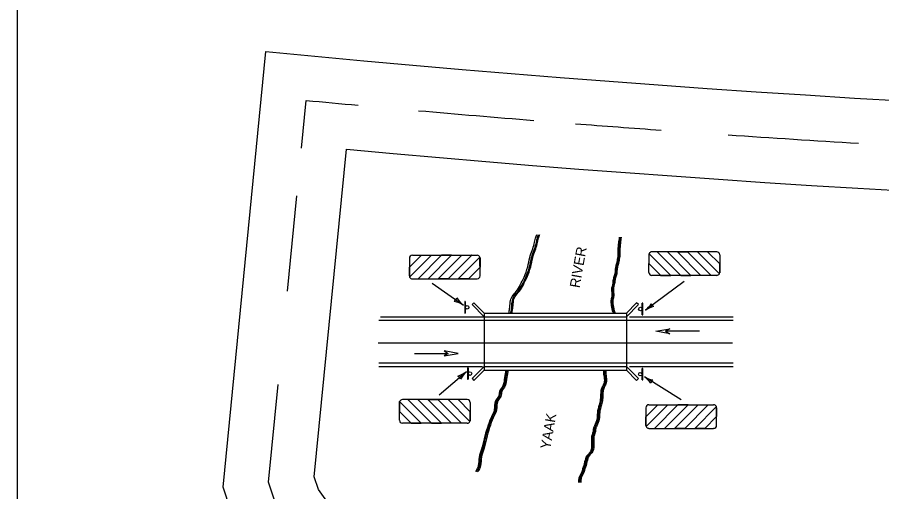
# Model space of a CAD drawing. Extents: x 49991.4 to 50021, y 49987.6 to 50011.4.
# Drawn here: x 50000.336 to 50002.261, y 50007.015 to 50008.071 of the extents above; entities that cross this region are included whole.
import ezdxf

# ---------------------------------------------------------------- set-up
doc = ezdxf.new("R2010")
doc.units = 0
for name, color, linetype in [('Level 1', 7, 'Continuous'), ('Level 2', 7, 'Continuous'), ('Level 3', 7, 'Continuous'), ('Level 4', 7, 'Continuous'), ('Level 5', 7, 'Continuous'), ('Level 7', 7, 'Continuous'), ('Level 8', 7, 'Continuous')]:
    doc.layers.add(name, color=color, linetype=linetype)

msp = doc.modelspace()

# ---------------------------------------------------------------- linework, layer by layer
at = {"layer": 'Level 1'}
for p, q in [((50001.3323, 50007.4382), (50001.3323, 50007.4126)), ((50001.3336, 50007.4382), (50001.3323, 50007.4382)), ((50001.3324, 50007.4382), (50001.3324, 50007.4126)), ((50001.3326, 50007.4382), (50001.3326, 50007.4126)), ((50001.3327, 50007.4382), (50001.3327, 50007.4126)), ((50001.3329, 50007.4382), (50001.3329, 50007.4126)), ((50001.333, 50007.4382), (50001.333, 50007.4126)), ((50001.3332, 50007.4382), (50001.3332, 50007.4126)), ((50001.3333, 50007.4382), (50001.3333, 50007.4126)), ((50001.3336, 50007.4382), (50001.3336, 50007.4126)), ((50001.3485, 50007.4314), (50001.3525, 50007.4353)), ((50001.3753, 50007.4045), (50001.3485, 50007.4314)), ((50001.3525, 50007.4353), (50001.3753, 50007.4125)), ((50001.7151, 50007.4353), (50001.6923, 50007.4125)), ((50001.6923, 50007.4045), (50001.719, 50007.4314)), ((50001.719, 50007.4314), (50001.7151, 50007.4353)), ((50001.729, 50007.4344), (50001.7277, 50007.4344)), ((50001.7277, 50007.4089), (50001.7277, 50007.4344)), ((50001.7279, 50007.4089), (50001.7279, 50007.4344)), ((50001.728, 50007.4089), (50001.728, 50007.4344)), ((50001.7281, 50007.4089), (50001.7281, 50007.4344)), ((50001.7284, 50007.4089), (50001.7284, 50007.4344)), ((50001.7284, 50007.4089), (50001.7284, 50007.4344)), ((50001.7287, 50007.4089), (50001.7287, 50007.4344)), ((50001.7288, 50007.4089), (50001.7288, 50007.4344)), ((50001.729, 50007.4089), (50001.729, 50007.4344)), ((50001.3323, 50007.4126), (50001.3336, 50007.4126)), ((50001.3753, 50007.4125), (50001.6923, 50007.4125)), ((50001.3753, 50007.4125), (50001.3753, 50007.2857)), ((50001.3753, 50007.4045), (50001.6923, 50007.4045)), ((50001.6923, 50007.4125), (50001.6923, 50007.2857)), ((50001.7277, 50007.4089), (50001.729, 50007.4089)), ((50001.1409, 50007.3966), (50001.9305, 50007.3966)), ((50001.1409, 50007.3017), (50001.9305, 50007.3017)), ((50001.3387, 50007.2908), (50001.3387, 50007.2652)), ((50001.3399, 50007.2908), (50001.3387, 50007.2908)), ((50001.3388, 50007.2908), (50001.3388, 50007.2652)), ((50001.339, 50007.2908), (50001.339, 50007.2652)), ((50001.3391, 50007.2908), (50001.3391, 50007.2652)), ((50001.3393, 50007.2908), (50001.3393, 50007.2652)), ((50001.3395, 50007.2908), (50001.3395, 50007.2652)), ((50001.3396, 50007.2908), (50001.3396, 50007.2652)), ((50001.3398, 50007.2908), (50001.3398, 50007.2652)), ((50001.3399, 50007.2908), (50001.3399, 50007.2652)), ((50001.3753, 50007.2937), (50001.3485, 50007.2668)), ((50001.3525, 50007.2629), (50001.3753, 50007.2857)), ((50001.3753, 50007.2937), (50001.6923, 50007.2937)), ((50001.3753, 50007.2857), (50001.6923, 50007.2857)), ((50001.6923, 50007.2937), (50001.719, 50007.2668)), ((50001.7151, 50007.2629), (50001.6923, 50007.2857)), ((50001.7288, 50007.2894), (50001.7275, 50007.2894)), ((50001.7275, 50007.2639), (50001.7275, 50007.2894)), ((50001.7277, 50007.2639), (50001.7277, 50007.2894)), ((50001.7278, 50007.2639), (50001.7278, 50007.2894)), ((50001.728, 50007.2639), (50001.728, 50007.2894)), ((50001.7281, 50007.2639), (50001.7281, 50007.2894)), ((50001.7284, 50007.2639), (50001.7284, 50007.2894)), ((50001.7284, 50007.2639), (50001.7284, 50007.2894)), ((50001.7287, 50007.2639), (50001.7287, 50007.2894)), ((50001.7288, 50007.2639), (50001.7288, 50007.2894)), ((50001.3485, 50007.2668), (50001.3525, 50007.2629)), ((50001.719, 50007.2668), (50001.7151, 50007.2629)), ((50001.3387, 50007.2652), (50001.3399, 50007.2652)), ((50001.7275, 50007.2639), (50001.7288, 50007.2639))]:
    msp.add_line(p, q, dxfattribs=at)
msp.add_lwpolyline([(50008.6146, 50011.2628), (50000.3356, 50011.2628), (50000.3356, 50000.0624), (50008.6146, 50000.0624)], close=True, dxfattribs=at)
for points in [[(50001.3799, 50005.8788), (50001.3215, 50006.0357), (50001.2141, 50006.2028), (50001.0765, 50006.3734), (50000.9542, 50006.4839), (50000.9664, 50006.5396), (50000.9328, 50006.5667), (50000.9328, 50006.7245), (50000.9084, 50006.799), (50000.9055, 50006.8175), (50000.8262, 50006.9283), (50000.7939, 50007.0252), (50000.8896, 50007.995)], [(50000.9689, 50007.7798), (50000.9793, 50007.8859)], [(50001.5508, 50005.9931), (50001.5014, 50006.1257), (50001.3765, 50006.32), (50001.2223, 50006.5113), (50001.1745, 50006.5544), (50001.1883, 50006.6177), (50001.1328, 50006.6624), (50001.1328, 50006.7565), (50001.1035, 50006.8459), (50001.0958, 50006.8953), (50001.0064, 50007.0202), (50000.9971, 50007.048), (50001.0691, 50007.7771)], [(50000.9374, 50007.4612), (50000.9584, 50007.6736)], [(50001.3341, 50007.4235), (50001.3357, 50007.4219)], [(50001.7271, 50007.4236), (50001.7256, 50007.4252)], [(50001.3405, 50007.276), (50001.3422, 50007.2744)], [(50001.7269, 50007.2785), (50001.7253, 50007.2801)], [(50000.9585, 50006.9153), (50000.9163, 50006.9742), (50000.8955, 50007.0366), (50000.9169, 50007.2536)]]:
    msp.add_lwpolyline(points, dxfattribs=at)
for centre in [(50001.3376, 50007.4254), (50001.7236, 50007.4217), (50001.344, 50007.278), (50001.7234, 50007.2766)]:
    msp.add_circle(centre, 0.004, dxfattribs=at)
for radius, start, end in [(36.1468, 264.4363, 275.54852), (36.2468, 264.59416, 264.77729), (36.2468, 264.99114, 265.3982), (36.2468, 265.54598, 265.84775), (36.2468, 266.08454, 266.54488), (36.3468, 264.75129, 275.22467)]:
    msp.add_arc((50004.3941, 50043.9715), radius, start, end, dxfattribs=at)
for points in [[(50001.4305, 50007.4124), (50001.4323, 50007.4224), (50001.4379, 50007.4499), (50001.447, 50007.4607), (50001.4561, 50007.4754), (50001.4643, 50007.4927), (50001.4725, 50007.5156), (50001.4772, 50007.5366), (50001.4872, 50007.5667), (50001.4899, 50007.5795), (50001.4926, 50007.5876)], [(50001.4346, 50007.4123), (50001.4365, 50007.4223), (50001.4419, 50007.4497), (50001.4511, 50007.4607), (50001.4602, 50007.4753), (50001.4685, 50007.4926), (50001.4767, 50007.5154), (50001.4812, 50007.5365), (50001.4912, 50007.5665), (50001.494, 50007.5793), (50001.4967, 50007.5876)], [(50001.4373, 50007.4125), (50001.4391, 50007.4225), (50001.4446, 50007.4499), (50001.4538, 50007.4609), (50001.4629, 50007.4755), (50001.471, 50007.4928), (50001.4793, 50007.5156), (50001.4839, 50007.5366), (50001.4939, 50007.5667), (50001.4966, 50007.5795), (50001.4993, 50007.5878)], [(50001.6635, 50007.4125), (50001.6617, 50007.418), (50001.6589, 50007.4335), (50001.6589, 50007.4427), (50001.6608, 50007.4517), (50001.6599, 50007.4655), (50001.6626, 50007.4791), (50001.6635, 50007.4874), (50001.6662, 50007.4965), (50001.669, 50007.5147), (50001.6708, 50007.5239), (50001.6735, 50007.5357), (50001.6744, 50007.5467), (50001.6744, 50007.5576), (50001.6753, 50007.5686), (50001.6762, 50007.575), (50001.6771, 50007.5813)], [(50001.6658, 50007.4127), (50001.6639, 50007.4181), (50001.6612, 50007.4337), (50001.6612, 50007.4427), (50001.663, 50007.452), (50001.6621, 50007.4656), (50001.6649, 50007.4793), (50001.6658, 50007.4875), (50001.6685, 50007.4967), (50001.6712, 50007.5149), (50001.6731, 50007.524), (50001.6758, 50007.5359), (50001.6767, 50007.5468), (50001.6767, 50007.5578), (50001.6776, 50007.5687), (50001.6785, 50007.5752), (50001.6795, 50007.5816)], [(50001.6678, 50007.4125), (50001.666, 50007.418), (50001.6632, 50007.4335), (50001.6632, 50007.4427), (50001.6651, 50007.4517), (50001.6641, 50007.4655), (50001.6669, 50007.4791), (50001.6678, 50007.4874), (50001.6705, 50007.4965), (50001.6732, 50007.5147), (50001.6752, 50007.5239), (50001.6779, 50007.5357), (50001.6788, 50007.5467), (50001.6788, 50007.5576), (50001.6797, 50007.5686), (50001.6806, 50007.575), (50001.6815, 50007.5813)], [(50001.4237, 50007.2856), (50001.4209, 50007.2692), (50001.4173, 50007.251), (50001.41, 50007.2381), (50001.4072, 50007.2272), (50001.4008, 50007.2171), (50001.3981, 50007.197), (50001.3909, 50007.1797), (50001.3827, 50007.1578), (50001.3753, 50007.1331), (50001.3698, 50007.1094), (50001.3643, 50007.0921), (50001.3625, 50007.0729), (50001.3561, 50007.0593)], [(50001.4262, 50007.2858), (50001.4233, 50007.2693), (50001.4197, 50007.251), (50001.4125, 50007.2384), (50001.4097, 50007.2273), (50001.4034, 50007.2173), (50001.4005, 50007.1973), (50001.3932, 50007.1799), (50001.3851, 50007.158), (50001.3777, 50007.1334), (50001.3723, 50007.1096), (50001.3668, 50007.0923), (50001.365, 50007.0731), (50001.3585, 50007.0594)], [(50001.4287, 50007.2856), (50001.426, 50007.2692), (50001.4224, 50007.251), (50001.4151, 50007.2381), (50001.4124, 50007.2272), (50001.4059, 50007.2171), (50001.4032, 50007.197), (50001.3959, 50007.1797), (50001.3877, 50007.1578), (50001.3804, 50007.1331), (50001.3749, 50007.1094), (50001.3694, 50007.0921), (50001.3675, 50007.0729), (50001.3612, 50007.0593)], [(50001.6414, 50007.2857), (50001.6414, 50007.2766), (50001.6433, 50007.263), (50001.6405, 50007.2519), (50001.6369, 50007.2447), (50001.6351, 50007.2355), (50001.6342, 50007.22), (50001.6315, 50007.2081), (50001.6278, 50007.1908), (50001.6269, 50007.1762), (50001.6213, 50007.1616), (50001.6186, 50007.1533), (50001.6186, 50007.1524), (50001.615, 50007.1379), (50001.615, 50007.1178), (50001.6105, 50007.1013), (50001.6041, 50007.0949), (50001.5994, 50007.0813), (50001.5949, 50007.0658), (50001.5922, 50007.0575), (50001.5867, 50007.0456), (50001.5858, 50007.0356)], [(50001.6438, 50007.2859), (50001.6438, 50007.2768), (50001.6456, 50007.2631), (50001.6429, 50007.2522), (50001.6393, 50007.2448), (50001.6375, 50007.2357), (50001.6366, 50007.2202), (50001.6338, 50007.2083), (50001.6302, 50007.191), (50001.6293, 50007.1763), (50001.6237, 50007.1617), (50001.621, 50007.1535), (50001.621, 50007.1526), (50001.6174, 50007.138), (50001.6174, 50007.118), (50001.6128, 50007.1016), (50001.6064, 50007.0951), (50001.6018, 50007.0814), (50001.5973, 50007.0659), (50001.5946, 50007.0577), (50001.5891, 50007.0458), (50001.5882, 50007.0358)], [(50001.6438, 50007.2859), (50001.6438, 50007.2768), (50001.6456, 50007.2631), (50001.6429, 50007.2522), (50001.6393, 50007.2448), (50001.6375, 50007.2357), (50001.6366, 50007.2202), (50001.6338, 50007.2083), (50001.6302, 50007.191), (50001.6293, 50007.1763), (50001.6237, 50007.1617), (50001.621, 50007.1535), (50001.621, 50007.1526), (50001.6174, 50007.138), (50001.6174, 50007.118), (50001.6128, 50007.1016), (50001.6064, 50007.0951), (50001.6018, 50007.0814), (50001.5973, 50007.0659), (50001.5946, 50007.0577), (50001.5891, 50007.0458), (50001.5882, 50007.0358)], [(50001.6465, 50007.2859), (50001.6465, 50007.2768), (50001.6483, 50007.2631), (50001.6456, 50007.2522), (50001.642, 50007.2448), (50001.6402, 50007.2357), (50001.6393, 50007.2202), (50001.6366, 50007.2083), (50001.6329, 50007.191), (50001.632, 50007.1763), (50001.6265, 50007.1617), (50001.6237, 50007.1535), (50001.6237, 50007.1526), (50001.6201, 50007.138), (50001.6201, 50007.118), (50001.6155, 50007.1016), (50001.6092, 50007.0951), (50001.6046, 50007.0814), (50001.6, 50007.0659), (50001.5973, 50007.0577), (50001.5918, 50007.0458), (50001.5909, 50007.0358)]]:
    msp.add_spline(points, degree=3, dxfattribs=at)
at = {"layer": 'Level 3'}
for p, q in [((50001.2598, 50007.4793), (50001.3293, 50007.4301)), ((50001.821, 50007.4826), (50001.7347, 50007.419)), ((50001.2756, 50007.2305), (50001.336, 50007.2829)), ((50001.8142, 50007.2193), (50001.7325, 50007.2706))]:
    msp.add_line(p, q, dxfattribs=at)
for centre, radius, start, end in [((50001.2999, 50007.451), 0.0154, 306.8721, 342.5944), ((50001.3675, 50007.4797), 0.0625, 212.1892, 232.3728), ((50001.2942, 50007.3749), 0.0655, 57.5606, 76.8104), ((50001.6975, 50007.4647), 0.059, 309.2289, 328.4787), ((50001.7663, 50007.3724), 0.0563, 103.8576, 124.0411), ((50001.7609, 50007.4383), 0.0139, 198.5404, 234.2627), ((50001.297, 50007.3318), 0.0625, 288.3958, 308.5793), ((50001.3088, 50007.2593), 0.0154, 23.0786, 58.8009), ((50001.3814, 50007.2356), 0.0655, 133.7671, 153.0169), ((50001.7007, 50007.2242), 0.0563, 35.3328, 55.5163), ((50001.7614, 50007.322), 0.059, 240.7041, 259.9539), ((50001.76, 50007.2534), 0.0139, 130.0156, 165.738)]:
    msp.add_arc(centre, radius, start, end, dxfattribs=at)
at = {"layer": 'Level 4'}
for p, q in [((50001.1444, 50007.4045), (50001.3753, 50007.4045)), ((50001.6996, 50007.4045), (50001.9305, 50007.4045)), ((50001.1409, 50007.2937), (50001.3718, 50007.2937)), ((50001.6996, 50007.2937), (50001.9305, 50007.2937))]:
    msp.add_line(p, q, dxfattribs=at)
at = {"layer": 'Level 5'}
msp.add_line((50001.1391, 50007.3467), (50001.9287, 50007.3467), dxfattribs=at)
at = {"layer": 'Level 7'}
for p, q in [((50001.855, 50007.3722), (50001.7796, 50007.3722)), ((50001.2202, 50007.323), (50001.2957, 50007.323))]:
    msp.add_line(p, q, dxfattribs=at)
for points in [[(50001.7891, 50007.3666), (50001.7577, 50007.3722), (50001.7891, 50007.3777), (50001.7796, 50007.3722)], [(50001.2861, 50007.3176), (50001.3175, 50007.323), (50001.2861, 50007.3287), (50001.2957, 50007.323)]]:
    msp.add_lwpolyline(points, close=True, dxfattribs=at)
at = {"layer": 'Level 8'}
for p, q in [((50001.209, 50007.5145), (50001.2358, 50007.5414)), ((50001.2583, 50007.5414), (50001.2096, 50007.4927)), ((50001.2156, 50007.5413), (50001.36, 50007.5413)), ((50001.2807, 50007.5414), (50001.2282, 50007.4888)), ((50001.2355, 50007.5414), (50001.2583, 50007.5414)), ((50001.2505, 50007.4888), (50001.3031, 50007.5414)), ((50001.273, 50007.4888), (50001.3256, 50007.5414)), ((50001.3031, 50007.5414), (50001.2807, 50007.5414)), ((50001.348, 50007.5414), (50001.2955, 50007.4888)), ((50001.318, 50007.4888), (50001.3662, 50007.5371)), ((50001.3256, 50007.5414), (50001.348, 50007.5414)), ((50001.3666, 50007.4954), (50001.3662, 50007.5371)), ((50001.7425, 50007.503), (50001.743, 50007.5447)), ((50001.7425, 50007.5424), (50001.7425, 50007.5226)), ((50001.7913, 50007.4964), (50001.743, 50007.5447)), ((50001.8935, 50007.5489), (50001.7491, 50007.5489)), ((50001.7836, 50007.5489), (50001.7611, 50007.5489)), ((50001.7611, 50007.5489), (50001.8136, 50007.4964)), ((50001.8361, 50007.4964), (50001.7836, 50007.5489)), ((50001.8585, 50007.4964), (50001.806, 50007.5489)), ((50001.806, 50007.5489), (50001.8284, 50007.5489)), ((50001.8284, 50007.5489), (50001.881, 50007.4964)), ((50001.8736, 50007.5489), (50001.8508, 50007.5489)), ((50001.8508, 50007.5489), (50001.8996, 50007.5003)), ((50001.9002, 50007.5222), (50001.8733, 50007.5489)), ((50001.9002, 50007.5424), (50001.9002, 50007.5019)), ((50001.2091, 50007.5348), (50001.2091, 50007.4943)), ((50001.3666, 50007.5348), (50001.3666, 50007.515)), ((50001.7425, 50007.5227), (50001.7688, 50007.4964)), ((50001.9002, 50007.503), (50001.9002, 50007.5222)), ((50001.209, 50007.4953), (50001.209, 50007.5145)), ((50001.3666, 50007.5151), (50001.3404, 50007.4888)), ((50001.9002, 50007.503), (50001.9002, 50007.503)), ((50001.2091, 50007.4954), (50001.209, 50007.4953)), ((50001.2156, 50007.4888), (50001.36, 50007.4888)), ((50001.2282, 50007.4888), (50001.2505, 50007.4888)), ((50001.2955, 50007.4888), (50001.273, 50007.4888)), ((50001.3405, 50007.4888), (50001.318, 50007.4888)), ((50001.318, 50007.4888), (50001.318, 50007.4888)), ((50001.8935, 50007.4964), (50001.7491, 50007.4964)), ((50001.7686, 50007.4964), (50001.7911, 50007.4964)), ((50001.7911, 50007.4964), (50001.7913, 50007.4964)), ((50001.8136, 50007.4964), (50001.8361, 50007.4964)), ((50001.881, 50007.4964), (50001.8585, 50007.4964)), ((50001.1869, 50007.1741), (50001.1873, 50007.2159)), ((50001.1869, 50007.2135), (50001.1869, 50007.1938)), ((50001.2355, 50007.1676), (50001.1873, 50007.2159)), ((50001.3378, 50007.2201), (50001.1934, 50007.2201)), ((50001.2279, 50007.2201), (50001.2055, 50007.2201)), ((50001.2055, 50007.2201), (50001.258, 50007.1676)), ((50001.2805, 50007.1676), (50001.2279, 50007.2201)), ((50001.3029, 50007.1676), (50001.2504, 50007.2201)), ((50001.2504, 50007.2201), (50001.2727, 50007.2201)), ((50001.2727, 50007.2201), (50001.3252, 50007.1676)), ((50001.318, 50007.2201), (50001.2952, 50007.2201)), ((50001.2952, 50007.2201), (50001.3439, 50007.1714)), ((50001.3445, 50007.1932), (50001.3176, 50007.2201)), ((50001.3444, 50007.2135), (50001.3444, 50007.1731)), ((50001.7356, 50007.1819), (50001.7625, 50007.2087)), ((50001.785, 50007.2087), (50001.7362, 50007.16)), ((50001.7422, 50007.2087), (50001.8867, 50007.2087)), ((50001.8073, 50007.2087), (50001.7548, 50007.1561)), ((50001.7622, 50007.2087), (50001.785, 50007.2087)), ((50001.7773, 50007.1561), (50001.8298, 50007.2087)), ((50001.7997, 50007.1561), (50001.8522, 50007.2087)), ((50001.8298, 50007.2087), (50001.8073, 50007.2087)), ((50001.8747, 50007.2087), (50001.8222, 50007.1561)), ((50001.8522, 50007.2087), (50001.8747, 50007.2087)), ((50001.1869, 50007.1938), (50001.2131, 50007.1676)), ((50001.3445, 50007.1741), (50001.3445, 50007.1932)), ((50001.7356, 50007.2021), (50001.7356, 50007.1616)), ((50001.8445, 50007.1561), (50001.8928, 50007.2044)), ((50001.8933, 50007.1627), (50001.8928, 50007.2044)), ((50001.8933, 50007.2021), (50001.8933, 50007.1823)), ((50001.3444, 50007.1741), (50001.3445, 50007.1741)), ((50001.7356, 50007.1626), (50001.7356, 50007.1819)), ((50001.8933, 50007.1824), (50001.867, 50007.1561)), ((50001.3378, 50007.1676), (50001.1934, 50007.1676)), ((50001.213, 50007.1676), (50001.2355, 50007.1676)), ((50001.2355, 50007.1676), (50001.2355, 50007.1676)), ((50001.258, 50007.1676), (50001.2805, 50007.1676)), ((50001.3252, 50007.1676), (50001.3029, 50007.1676)), ((50001.7356, 50007.1627), (50001.7356, 50007.1626)), ((50001.7422, 50007.1561), (50001.8867, 50007.1561)), ((50001.7548, 50007.1561), (50001.7773, 50007.1561)), ((50001.8222, 50007.1561), (50001.7997, 50007.1561)), ((50001.8447, 50007.1561), (50001.8445, 50007.1561)), ((50001.8672, 50007.1561), (50001.8447, 50007.1561))]:
    msp.add_line(p, q, dxfattribs=at)
for points in [[(50001.3479, 50007.5412), (50001.3479, 50007.5412), (50001.3477, 50007.5414)], [(50001.7612, 50007.5489), (50001.7612, 50007.5489), (50001.7614, 50007.5489)], [(50001.2055, 50007.2199), (50001.2055, 50007.2199), (50001.2057, 50007.2201)], [(50001.8745, 50007.2085), (50001.8745, 50007.2085), (50001.8744, 50007.2087)]]:
    msp.add_lwpolyline(points, dxfattribs=at)
for centre, start, end in [((50001.2156, 50007.5348), 90, 180), ((50001.3601, 50007.5348), 20.6972, 90), ((50001.3601, 50007.5348), 20.6972, 20.7258), ((50001.3601, 50007.5348), 0, 20.6983), ((50001.7491, 50007.5424), 159.3017, 180), ((50001.7491, 50007.5424), 90, 159.3028), ((50001.7491, 50007.5424), 159.2742, 159.3028), ((50001.8936, 50007.5424), 0, 90), ((50001.7491, 50007.503), 180, 270), ((50001.8936, 50007.503), 270, 335.861), ((50001.8936, 50007.503), 335.9032, 0), ((50001.2156, 50007.4954), 180, 204.0968), ((50001.2156, 50007.4954), 204.139, 270), ((50001.3601, 50007.4954), 270, 360), ((50001.1934, 50007.2135), 159.3017, 180), ((50001.1934, 50007.2135), 90, 159.3028), ((50001.1934, 50007.2135), 159.2742, 159.3028), ((50001.3379, 50007.2135), 0, 90), ((50001.7423, 50007.2021), 90, 180), ((50001.8867, 50007.2021), 20.6972, 90), ((50001.8867, 50007.2021), 20.6972, 20.7258), ((50001.8867, 50007.2021), 0, 20.6983), ((50001.1934, 50007.1741), 180, 270), ((50001.3379, 50007.1741), 270, 335.861), ((50001.3379, 50007.1741), 335.9032, 0), ((50001.7423, 50007.1627), 180, 204.0968), ((50001.7423, 50007.1627), 204.139, 270), ((50001.8867, 50007.1627), 270, 360)]:
    msp.add_arc(centre, 0.00657, start, end, dxfattribs=at)

# ---------------------------------------------------------------- texts
at = {"layer": 'Level 2'}
for s, rotation, p in [('RIVER', 79.9154, (50001.588, 50007.4675)), ('YAAK', 79.9219, (50001.5225, 50007.1084))]:
    msp.add_text(s, height=0.0225, rotation=rotation, dxfattribs=at).set_placement(p)

doc.saveas('drawing.dxf')
